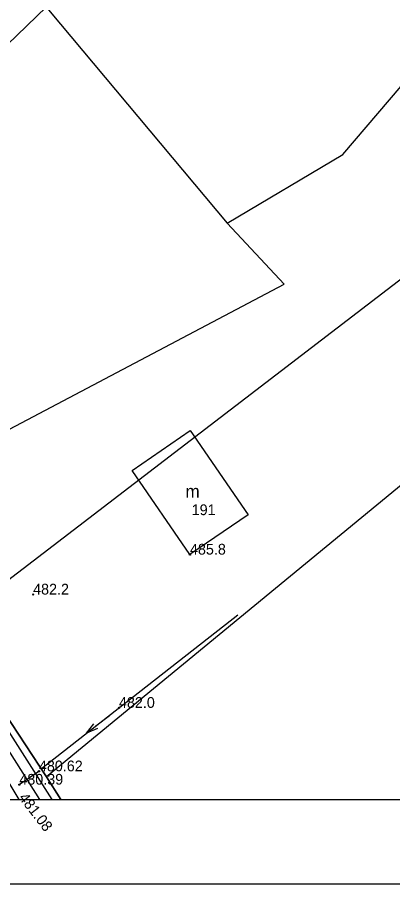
# Model space of a CAD drawing. Extents: x 4650326 to 4650741, y 5341000 to 5341288.
# Drawn here: x 4650427.1 to 4650479.7, y 5341000.2 to 5341121.4 of the extents above; entities that cross this region are included whole.
import ezdxf

# ---------------------------------------------------------------- set-up
doc = ezdxf.new("R2010")
doc.units = 0
for name, color, linetype in [('Warstwa 20', 7, 'Continuous'), ('Warstwa 25', 7, 'Continuous'), ('Warstwa 27', 7, 'Continuous'), ('Warstwa 3', 7, 'Continuous'), ('Warstwa 35', 7, 'Continuous'), ('Warstwa 4', 7, 'Continuous'), ('Warstwa 45', 7, 'Continuous'), ('Warstwa 48', 7, 'Continuous'), ('Warstwa 50', 7, 'Continuous'), ('Warstwa 53', 7, 'Continuous'), ('Warstwa 9', 7, 'Continuous')]:
    doc.layers.add(name, color=color, linetype=linetype)

msp = doc.modelspace()

# ---------------------------------------------------------------- linework, layer by layer
at = {"layer": 'Warstwa 20'}
msp.add_lwpolyline([(4650356.17, 5341132), (4650376.51, 5341097.46), (4650399.08, 5341059.32), (4650417.65, 5341028.07), (4650427.373, 5341012.003)], dxfattribs=at)
at = {"layer": 'Warstwa 25'}
for p, q in [((4650490.79, 5341180.52), (4650388.7, 5341081.84)), ((4650534.87, 5341100.4), (4650431.25, 5341015.16)), ((4650431.25, 5341015.16), (4650420.28, 5341031.75)), ((4650431.25, 5341015.16), (4650420.28, 5341031.75)), ((4650433.254, 5341012.003), (4650431.25, 5341015.16)), ((4650433.254, 5341012.003), (4650431.25, 5341015.16))]:
    msp.add_line(p, q, dxfattribs=at)
at = {"layer": 'Warstwa 27'}
for p, q in [((4650413.7, 5341143.83), (4650456.53, 5341092.63)), ((4650472.7, 5341102.26), (4650504.19, 5341139.15)), ((4650417.43, 5341036.27), (4650517.45, 5341112.93)), ((4650456.53, 5341092.63), (4650472.7, 5341102.26)), ((4650456.53, 5341092.63), (4650464.48, 5341084.1)), ((4650406.56, 5341053.51), (4650464.48, 5341084.1)), ((4650420.28, 5341031.75), (4650431.25, 5341015.16)), ((4650420.28, 5341031.75), (4650431.25, 5341015.16)), ((4650431.25, 5341015.16), (4650433.254, 5341012.003)), ((4650431.25, 5341015.16), (4650433.254, 5341012.003))]:
    msp.add_line(p, q, dxfattribs=at)
at = {"layer": 'Warstwa 3'}
for p, q in [((4650443.23, 5341058.02), (4650451.36, 5341063.6)), ((4650451.36, 5341063.6), (4650459.44, 5341051.84)), ((4650451.31, 5341046.26), (4650443.23, 5341058.02)), ((4650459.44, 5341051.84), (4650451.31, 5341046.26))]:
    msp.add_line(p, q, dxfattribs=at)
at = {"layer": 'Warstwa 35'}
for p, q in [((4650432.008, 5341012.003), (4650406.68, 5341051.8)), ((4650405.44, 5341051), (4650430.254, 5341012.003)), ((4650427.43, 5341014.06), (4650430.17, 5341015.93))]:
    msp.add_line(p, q, dxfattribs=at)
at = {"layer": 'Warstwa 45'}
for centre in [(4650451.31, 5341046.26), (4650429.36, 5341040.67), (4650441.37, 5341024.81), (4650430.17, 5341015.93), (4650427.43, 5341014.06)]:
    msp.add_circle(centre, 0.09, dxfattribs=at)
at = {"layer": 'Warstwa 48'}
for points in [[(4650326.19, 5341000.203), (4650737.19, 5341000.203), (4650737.19, 5341288.203), (4650326.19, 5341288.203)], [(4650326.19, 5341012.003), (4650737.19, 5341012.003), (4650737.19, 5341261.537), (4650326.19, 5341261.537)]]:
    msp.add_lwpolyline(points, close=True, dxfattribs=at)
at = {"layer": 'Warstwa 53'}
msp.add_line((4650430.51, 5341016.32), (4650458, 5341037.82), dxfattribs=at)
at = {"layer": 'Warstwa 9'}
for p, q in [((4650436.849, 5341021.275), (4650437.879, 5341022.563)), ((4650440.03, 5341023.7), (4650438.122, 5341022.245)), ((4650438.364, 5341021.927), (4650436.849, 5341021.275))]:
    msp.add_line(p, q, dxfattribs=at)

# ---------------------------------------------------------------- texts
at = {"layer": 'Warstwa 4'}
for s, height, p in [('m', 1.8, (4650450.67, 5341054.2)), ('191', 1.5, (4650451.55, 5341051.78))]:
    msp.add_text(s, height=height, dxfattribs=at).set_placement(p)
at = {"layer": 'Warstwa 45'}
for s, p in [('485.8', (4650451.31, 5341046.26)), ('482.2', (4650429.36, 5341040.67)), ('482.0', (4650441.37, 5341024.81))]:
    msp.add_text(s, height=1.5, dxfattribs=at).set_placement(p)
at = {"layer": 'Warstwa 50'}
for s, p in [('480.62', (4650430.17, 5341015.93)), ('480.39', (4650427.43, 5341014.06))]:
    msp.add_text(s, height=1.5, dxfattribs=at).set_placement(p)
msp.add_text('481.08', height=1.5, rotation=307.7176, dxfattribs=at).set_placement((4650427.27, 5341012.21))

doc.saveas('drawing.dxf')
